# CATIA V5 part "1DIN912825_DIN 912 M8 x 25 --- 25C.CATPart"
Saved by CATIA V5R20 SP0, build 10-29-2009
Part number: 1DIN912825_DIN 912 M8 x 25 --- 25C
Revision: ANY
Definition: UNKNOWN
Nomenclature: 1DIN912825_DIN 912 M8 x 25 --- 25C
Source: Unknown
Bounding box of the stored display mesh (mm): x 0 to 33, y -6.337 to 6.337, z -6.5 to 6.5
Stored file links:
  C:\Users\Utente\Desktop\IO LAVORO\3D X SITO CF\CUMSA\3D files PR.233230\PR 263230\1DIN912825_DIN 912 M8 x 25 --- 25C.CATPart
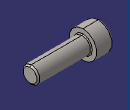
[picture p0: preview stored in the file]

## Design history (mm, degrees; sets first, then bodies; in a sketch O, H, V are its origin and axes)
Body1 "Hex" (main body)
  Solid1: solid without history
